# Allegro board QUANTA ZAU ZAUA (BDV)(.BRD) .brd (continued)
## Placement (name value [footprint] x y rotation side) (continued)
R342  EV_SP@100K_5%_4  [R0402]  113.27 80.25 0 top
R343  EV_SP@100K_5%_4  [R0402]  111.87 80.63 90 top
R344  EV_SP@100K_5%_4  [R0402]  88.2 95.62 0 bottom
R345  EV_SP@100K_5%_4  [R0402]  88.2 94.6 0 bottom
R346  EV_SP@100K_5%_4  [R0402]  88.2 96.63 0 bottom
R347  EV_SP@100K_5%_4  [R0402]  88.2 97.65 0 bottom
R348  EV_SP@100K_5%_4  [R0402]  88.37 92.64 0 bottom
R349  EV_SP@100K_5%_4  [R0402]  88.2 93.62 0 bottom
R350  EV_SP@30.1K_1%_4  [R0402]  110.91 82.41 90 top
R351  *EV@100K_5%_4  [R0402]  111.87 82.41 90 top
R352  EV_SP@100K_5%_4  [R0402]  113.27 81.27 180 top
R353  EV_SP@100K_5%_4  [R0402]  90.49 96.76 180 bottom
R354  EV_SP@100K_5%_4  [R0402]  90.49 95.74 180 bottom
R355  EV_SP@100K_5%_4  [R0402]  90.49 97.78 180 bottom
R356  EV_SP@100K_5%_4  [R0402]  90.49 98.79 180 bottom
R357  EV_SP@100K_5%_4  [R0402]  90.49 93.59 180 bottom
R358  EV_SP@100K_5%_4  [R0402]  90.49 94.73 180 bottom
R359  *0_5%_4  [R0402]  176.08 26.15 180 top
R361  4.7K_5%_2  [R0201]  192.57 32.22 90 top
R362  N17@4.7K_5%_4  [R0402]  105.6 85.97 90 top
R363  EV@2.2K_5%_2  [R0201]  95.97 89.65 270 bottom
R364  N17@0_5%_4  [R0402]  94.3 88.12 270 bottom
R365  N17@4.7K_5%_4  [R0402]  104.76 88.38 270 top
R366  EV@2.2K_5%_2  [R0201]  95.26 89.65 270 bottom
R367  EV@2.2K_5%_2  [R0201]  94.55 89.65 270 bottom
R368  EV@2.2K_5%_2  [R0201]  93.84 89.65 270 bottom
R369  4.7K_5%_2  [R0201]  191.84 32.21 90 top
R370  N17@0_5%_2  [R0201]  98.08 96.13 180 top
R372  N17@0_5%_2  [R0201]  88.67 98.83 180 top
R373  N17@0_5%_2  [R0201]  90.23 97.14 180 top
R374  N17@0_5%_2  [R0201]  90.05 93.16 180 top
R376  N17@0_5%_2  [R0201]  90.23 95.72 180 top
R378  EV@10K_1%_4  [R0402]  201.25 16.35 90 top
R380  43_5%_4  [R0402]  179.26 32.24 0 top
R382  *EV@0_5%_4  [R0402]  98.74 123.43 0 top
R383  4.7K_5%_2  [R0201]  190.69 32.29 90 top
R384  *EV@short_4  [S0402]  103.52 123.14 180 top
R385  *EV@4.7K_5%_4  [R0402]  98.74 125.46 180 top
R386  EV@10K_5%_4  [R0402]  91.93 118.15 270 bottom
R391  EV@10K_1%_4  [R0402]  88.2 90.41 0 bottom
R394  EV@10K_1%_4  [R0402]  87.69 99.17 270 top
R395  EV@10K_1%_4  [R0402]  98.74 124.45 0 top
R396  EV@10K_1%_4  [R0402]  96.4 117.79 0 bottom
R397  EV@10K_1%_4  [R0402]  88.07 94.6 0 top
R398  EV@100K_1%_4  [R0402]  89.85 89.39 180 bottom
R399  EV@10K_1%_4  [R0402]  88.23 91.41 0 bottom
R402  *22_5%_4  [R0402]  181.04 23.35 180 top
R403  EV@10K_1%_4  [R0402]  88.07 93.59 0 top
R404  *EV@10K_1%_4  [R0402]  88.07 95.62 0 top
R405  EV@120_1%_4  [R0402]  132.78 97.65 90 bottom
R406  EV@120_1%_4  [R0402]  131.63 102.35 180 bottom
R407  EV@549_1%_4  [R0402]  133.92 100.06 0 top
R410  EV@1.33K_1%_4  [R0402]  133.92 99.05 0 top
R411  EV@931_1%_4  [R0402]  133.92 101.08 0 top
R414  TPC@20K_1%_4  [R0402]  16.57 47.23 90 top
R415  TPC@39K_1%_4  [R0402]  16.57 49.01 90 top
R416  TPC@100K_5%_4  [R0402]  23.56 46.85 90 top
R417  TPC@10K_5%_4  [R0402]  23.94 49.39 0 top
R418  TPC@10K_5%_4  [R0402]  23.94 48.37 0 top
R419  TPC@0_5%_2  [R0201]  20.02 51.69 180 top
R420  TPC@0_5%_2  [R0201]  20.02 52.64 180 top
R421  *short_4  [S0402]  22.54 52.44 180 top
R422  *short_4  [S0402]  22.54 53.45 180 top
R423  *short_4  [S0402]  23.68 57.9 180 top
R424  *short_4  [S0402]  23.68 56.88 180 top
R425  *short_4  [S0402]  22.16 35.17 180 top
R426  *short_4  [S0402]  22.16 34.15 180 top
R427  *short_4  [S0402]  22.16 32.12 180 top
R428  *short_4  [S0402]  22.16 33.13 180 top
R429  *short_4  [S0402]  23.3 36.94 180 top
R430  *short_4  [S0402]  23.3 37.96 180 top
R436  *short_4  [S0402]  57.62 105.93 90 top
R439  *1K_5%_4  [R0402]  53.38 103.57 90 top
R440  *1K_5%_4  [R0402]  58.48 111.82 270 top
R441  1K_1%_4  [R0402]  54.37 103.57 270 top
R442  100K_1%_4  [R0402]  57.69 107.3 180 top
R443  10_5%_4  [R0402]  52.39 103.57 90 top
R445  *short_4  [S0402]  82.1 92.95 180 bottom
R446  100K_1%_4  [R0402]  80.58 94.22 0 bottom
R447  100K_5%_4  [R0402]  202.12 38.47 90 bottom
R448  256@0_5%_4  [R0402]  211.39 31.86 270 top
R449  255@0_5%_4  [R0402]  213.42 32.37 0 top
R450  *short_6  [S0603]  197.83 33.97 0 bottom
R451  200K_1%_4  [R0402]  199.91 30.95 180 top
R452  255@100K_5%_4  [R0402]  200.17 29.97 90 bottom
R453  *256@0_5%_4  [R0402]  210.5 28.59 270 bottom
R454  *255@0_5%_4  [R0402]  211.49 28.59 270 bottom
R455  *short_6  [S0603]  208.39 27.65 0 bottom
R459  *short_4  [S0402]  208.67 26.07 90 bottom
R460  *short_4  [S0402]  202.68 26.9 315 top
R461  22_5%_4  [R0402]  207.71 26.07 270 bottom
R462  *0_5%_4  [R0402]  204.94 24.98 180 top
R463  *short_4  [S0402]  203.41 34.97 90 top
R464  *0_5%_4  [R0402]  210.63 35.67 180 top
R465  *0_5%_4  [R0402]  210.62 39.58 180 top
R467  *0_5%_4  [R0402]  210.63 34.66 180 top
R468  2.2K_5%_4  [R0402]  210.63 41.77 180 top
R469  *0_5%_4  [R0402]  210.63 37.71 180 top
R470  *short_4  [S0402]  207.33 33.87 0 top
R471  2.2K_5%_4  [R0402]  210.63 42.79 180 top
R472  62_1%_4  [R0402]  213.29 46.8 0 top
R473  62_1%_4  [R0402]  215.63 45.5 90 top
R474  *10K_5%_4  [R0402]  211.67 46.87 270 top
R475  *10K_5%_4  [R0402]  214.67 43.78 90 top
R476  4.7K_5%_4  [R0402]  213.29 45.81 180 top
R477  4.7K_5%_4  [R0402]  215.63 43.78 90 top
R478  1K_5%_4  [R0402]  210.98 28.26 180 top
R479  *10K_5%_4  [R0402]  210.83 30.31 270 bottom
R480  *short_6  [S0603]  119.42 17.97 270 top
R481  *short_6  [S0603]  117.99 17.97 270 top
R482  *short_6  [S0603]  116.55 17.97 270 top
R483  *short_6  [S0603]  115.12 17.97 270 top
R484  *150_1%_4  [R0402]  14.79 79.36 90 bottom
R486  *150_1%_4  [R0402]  14.79 77.33 90 bottom
R487  *150_1%_4  [R0402]  14.79 75.3 90 bottom
R489  *150_1%_4  [R0402]  14.79 81.39 90 bottom
R490  2.2K_5%_4  [R0402]  23.61 67.93 90 top
R491  2.2K_5%_4  [R0402]  23.53 69.89 270 top
R494  2.2K_5%_4  [R0402]  18.6 83.81 90 top
R495  *HDD_R@4.7K_5%_4  [R0402]  215.71 13.7 270 top
R497  *HDD_R@4.7K_5%_4  [R0402]  214.69 15.73 90 top
R498  *HDD_R@4.7K_5%_4  [R0402]  214.69 13.7 270 top
R499  HDD_R@4.7K_5%_4  [R0402]  213.68 12.81 90 top
R500  *HDD_R@4.7K_5%_4  [R0402]  215.33 12.31 0 top
R502  2.2K_5%_4  [R0402]  19.75 83.81 90 top
R503  *HDD_R@4.7K_5%_4  [R0402]  206.94 13.45 270 top
R504  HDD_R@4.7K_5%_4  [R0402]  207.07 15.95 0 top
R505  *HDD_R@4.7K_5%_4  [R0402]  205.04 15.1 180 top
R506  HDD_R@4.7K_5%_4  [R0402]  207.07 18.05 180 top
R507  HDMI_R@11K_1%_4  [R0402]  20.89 83.81 270 top
R508  2.49K_1%_4  [R0402]  41.74 109.16 180 top
R509  1K_5%_4  [R0402]  50.28 103.59 90 top
R510  15K_1%_4  [R0402]  48.91 103.59 270 top
R511  10_5%_4  [R0402]  45.88 109.59 90 top
R512  0_5%_4  [R0402]  44.92 109.59 270 top
R513  *short_4  [S0402]  49.8 104.96 0 top
R516  75_1%_8  [R0805]  38.8 111.49 90 top
R517  75_1%_8  [R0805]  35.75 111.49 90 top
R518  75_1%_8  [R0805]  32.7 111.49 90 top
R519  75_1%_8  [R0805]  29.78 111.49 90 top
R557  *0_5%_4  [R0402]  95.49 26.9 270 top
R558  *short_4  [S0402]  94.96 28.75 90 top
R559  4.7K_5%_4  [R0402]  71.18 17.28 90 top
R560  *short_4  [S0402]  93.28 29.62 0 top
R561  *0_5%_4  [R0402]  92.8 28.65 180 top
R562  4.7K_5%_4  [R0402]  72.43 17.28 90 top
R566  4.7K_5%_4  [R0402]  75.68 16.67 0 top
R567  4.7K_5%_4  [R0402]  73.95 16.67 180 top
R572  *short_4  [S0402]  69.84 22.87 180 bottom
R573  *short_4  [S0402]  70.93 15.61 0 top
R574  *10K_5%_4  [R0402]  68.44 23.25 90 bottom
R575  *short_8  [S0805]  175.25 28.36 180 top
R576  1K_5%_4  [R0402]  179.89 29.83 270 top
R579  KBL@10K_5%_4  [R0402]  198.05 19.34 270 bottom
R580  TPM@10K_1%_2  [R0201]  123.23 25.67 0 top
R582  *GS@short_4  [S0402]  50.02 21.45 180 top
R583  TPM@10K_1%_2  [R0201]  121.09 17.74 0 top
R586  TPM@10K_1%_2  [R0201]  121.12 21.14 270 top
R589  *short_4  [S0402]  51.6 18.6 180 top
R590  *GS@short_2  [S0201]  52 20.15 180 top
R591  *GS@short_2  [S0201]  58.23 23.4 180 top
R592  TPM@0_5%_2  [R0201]  126.4 16.55 0 top
R593  TPM@0_5%_2  [R0201]  123 24.57 270 top
R596  TPM@33_5%_2  [R0201]  122.29 24.57 270 top
R597  TPM@33_5%_2  [R0201]  121.65 19.85 0 top
R598  TPM@33_5%_2  [R0201]  121.63 16.42 0 top
R599  TPM@0_5%_2  [R0201]  121.83 21.14 270 top
R600  *TPM@1.2K_5%_2  [R0201]  129.7 20.48 180 top
R601  TPM@0_5%_2  [R0201]  123.73 24.57 270 top
R608  *PBA@0_5%_4  [R0402]  64.6 20.74 0 bottom
R609  PBA@10K_5%_2  [R0201]  66.48 24.67 180 bottom
R614  *short_4  [S0402]  55.59 22.54 180 bottom
R638  ODD@10K_5%_2  [R0201]  129.5 16.52 0 top
R639  *short_8  [S0805]  124.34 18.86 270 bottom
R640  ODD@33_5%_4  [R0402]  136.33 21.37 270 bottom
R641  *ODD@10K_5%_4  [R0402]  135.37 21.37 90 bottom
R645  *SSD@short_2  [S0201]  31.35 2.42 0 top
R646  *SSD@short_2  [S0201]  29.22 11.39 270 bottom
R647  *SSD@short_2  [S0201]  29.98 11.39 270 bottom
R648  *SSD@short_2  [S0201]  28.03 2.42 0 top
R649  SSD@100K_1%_4  [R0402]  23.4 6.31 270 top
R651  4.7K_5%_4  [R0402]  180.83 14.64 180 bottom
R652  4.7K_5%_4  [R0402]  180.83 15.61 180 bottom
R653  *SSD@short_2  [S0201]  13.57 3.19 180 top
R654  *SSD@0_5%_2  [R0201]  22.41 7.56 0 top
R655  *0_5%_4  [R0402]  196.2 18.22 180 bottom
R664  CNV@20K_1%_4  [R0402]  196.07 23.81 135 bottom
R665  CNV@22_1%_4  [R0402]  193.03 25.67 180 bottom
R667  CNV@22_1%_4  [R0402]  193.69 23.28 180 bottom
R670  *short_4  [S0402]  193.31 21.58 180 bottom
R671  *10K_5%_4  [R0402]  193.74 20.53 180 bottom
R672  *10K_5%_4  [R0402]  193.71 19.32 180 bottom
R673  *short_4  [S0402]  193.48 18.15 180 bottom
R674  *short_4  [S0402]  194.83 17.94 270 bottom
R675  *short_4  [S0402]  193.1 16.98 180 bottom
R676  CNV@75K_1%_4  [R0402]  154.11 21.75 270 top
R677  CNV@75K_1%_4  [R0402]  158.89 20.71 90 top
R678  CNV@75K_1%_4  [R0402]  149.06 24.22 0 top
R679  CNV@71.5K_1%_4  [R0402]  147.86 26.53 90 top
R696  *HDMI_R@short_2  [S0201]  16.22 74.76 180 top
R697  *HDMI_R@short_2  [S0201]  16.22 75.83 180 top
R698  *HDMI_R@short_2  [S0201]  16.22 76.67 180 top
R699  *HDMI_R@short_2  [S0201]  16.22 77.74 180 top
R700  *HDMI_R@short_2  [S0201]  16.22 78.83 180 top
R701  *HDMI_R@short_2  [S0201]  16.22 79.89 180 top
R702  *HDMI_R@short_2  [S0201]  16.22 80.86 180 top
R703  *HDMI_R@short_2  [S0201]  16.22 81.93 180 top
R706  HDMI_N@470_1%_2  [R0201]  14.79 81.9 180 top
R707  HDMI_N@470_1%_2  [R0201]  14.79 80.89 180 top
R708  HDMI_N@470_1%_2  [R0201]  14.92 79.87 90 top
R709  HDMI_N@470_1%_2  [R0201]  14.92 78.85 270 top
R710  HDMI_N@470_1%_2  [R0201]  14.79 77.84 180 top
R711  HDMI_N@470_1%_2  [R0201]  14.79 76.82 180 top
R712  HDMI_N@470_1%_2  [R0201]  14.79 75.81 180 top
R713  HDMI_N@470_1%_2  [R0201]  14.79 74.79 180 top
R720  33_5%_4  [R0402]  151.32 21.55 0 top
R732  *100K_5%_4  [R0402]  205.65 27.55 90 bottom
R733  256@100K_5%_4  [R0402]  198.49 30.34 0 bottom
R734  10K_5%_4  [R0402]  199.48 27.14 90 bottom
R735  22K_1%_4  [R0402]  197.22 32.37 270 bottom
R736  255@0_5%_4  [R0402]  195.57 34.38 0 bottom
R737  256@0_5%_4  [R0402]  195.57 35.35 0 bottom
R738  255@0_5%_4  [R0402]  199.91 22.74 90 bottom
R739  256@0_5%_4  [R0402]  199.88 24.57 0 bottom
R740  256@0_5%_4  [R0402]  200.14 25.79 0 bottom
R741  256@3.3K_5%_4  [R0402]  201.36 28.59 180 top
R742  256@3.3K_5%_4  [R0402]  200.82 27.35 0 bottom
R746  *HDMI_R@10K_5%_4  [R0402]  17.61 83.81 270 top
R747  HDMI_R@10K_5%_4  [R0402]  22.9 83.81 90 top
R748  *HDMI_R@0_5%_4  [R0402]  21.91 83.81 270 top
R749  HDMI_R@0_5%_4  [R0402]  16.62 84.24 90 top
R750  *short_4  [S0402]  21.96 85.23 0 top
R775  *short_4  [S0402]  25.08 61.2 180 top
R777  *short_4  [S0402]  25.08 60.18 180 top
R890  100K_5%_2  [R0201]  177.48 17.56 90 top
R894  *short_2  [S0201]  179.69 19.32 270 top
R895  33_5%_2  [R0201]  196.96 31.38 270 top
R956  33_5%_2  [R0201]  202.91 20.69 180 top
R960  33_5%_4  [R0402]  198.21 23.99 270 bottom
R1234  HDD_R@4.7K_5%_4  [R0402]  215.71 15.73 90 top
R1235  HDD_R@4.7K_5%_4  [R0402]  207.07 14.95 0 top
R1236  *HDD_R@4.7K_5%_4  [R0402]  207.07 17.08 0 top
R1237  *HDD_R@4.7K_5%_4  [R0402]  205.04 17.13 180 top
R1238  HDD_R@4.7K_5%_4  [R0402]  205.04 16.12 180 top
R1239  *HDD_R@short_4  [S0402]  206.18 11.54 90 top
R1250  20K_1%_4  [R0402]  18.4 85.66 90 top
R1284  HDMI_N@0_5%_2  [R0201]  25.59 74.92 0 top
R1285  HDMI_N@0_5%_2  [R0201]  25.59 76.06 0 top
R1286  HDMI_N@0_5%_2  [R0201]  25.59 76.82 0 top
R1287  HDMI_N@0_5%_2  [R0201]  25.59 77.96 0 top
R1288  HDMI_N@0_5%_2  [R0201]  25.59 78.73 0 top
R1289  HDMI_N@0_5%_2  [R0201]  25.59 79.87 0 top
R1290  HDMI_N@0_5%_2  [R0201]  25.59 80.63 0 top
R1291  HDMI_N@0_5%_2  [R0201]  25.59 81.77 0 top
R2088  MD@36_1%_4  [R0402]  34.73 101.79 90 top
R2089  MD@36_1%_4  [R0402]  35.77 101.79 90 top
R2090  MD@36_1%_4  [R0402]  33.67 101.79 90 top
R2091  MD@36_1%_4  [R0402]  32.62 101.79 90 top
R2092  MD@36_1%_4  [R0402]  31.58 101.79 90 top
R2099  MD@36_1%_4  [R0402]  41.92 99.86 90 top
R2100  MD@36_1%_4  [R0402]  40.91 99.86 90 top
R2101  MD@36_1%_4  [R0402]  38.95 99.37 90 top
R2102  MD@36_1%_4  [R0402]  32.52 99.4 90 top
R2103  MD@36_1%_4  [R0402]  33.87 99.4 90 top
R2104  MD@36_1%_4  [R0402]  37.93 99.38 90 top
R2105  MD@36_1%_4  [R0402]  35.9 99.4 90 top
R2106  MD@36_1%_4  [R0402]  34.89 99.4 90 top
R2107  MD@36_1%_4  [R0402]  36.91 99.39 90 top
R2109  MD@36_1%_4  [R0402]  38.41 97.21 90 top
R2110  MD@36_1%_4  [R0402]  39.38 97.19 90 top
R2111  MD@36_1%_4  [R0402]  33.59 97.21 90 top
R2112  MD@36_1%_4  [R0402]  29.76 95.8 180 top
R2114  MD@36_1%_4  [R0402]  29.76 94.78 180 top
R2116  MD@36_1%_4  [R0402]  29.76 93.77 180 top
R2117  MD@36_1%_4  [R0402]  29.76 92.75 180 top
R2118  MD@36_1%_4  [R0402]  29.76 91.73 180 top
R2119  MD@36_1%_4  [R0402]  29.76 90.72 180 top
R2121  MD@36_1%_4  [R0402]  29.76 89.7 180 top
R2124  MD@36_1%_4  [R0402]  29.79 88.69 180 top
R2126  MD@36_1%_4  [R0402]  29.77 87.65 180 top
R2130  MD@36_1%_4  [R0402]  29.76 86.63 180 top
R2132  MD@1.8K_1%_4  [R0402]  62.93 82.9 0 top
R2134  MD@0_5%_4  [R0402]  50.4 85.84 180 top
R2135  *MD@0_5%_4  [R0402]  65.06 85.1 0 top
R2136  MD@2.7_5%_6  [R0603]  65.22 83.15 270 top
R2137  MD@36_1%_4  [R0402]  28.94 62.27 90 top
R2138  MD@240_1%_4  [R0402]  50.4 84.82 180 top
R2140  MD@1.8K_1%_4  [R0402]  62.93 84.04 180 top
R2142  MD@24.9_1%_4  [R0402]  62.93 80.99 0 top
R2158  MD@0_5%_4  [R0402]  43.65 68.26 90 top
R2159  MD@240_1%_4  [R0402]  42.56 68.29 90 top
R2160  49.9_1%_4  [R0402]  93.03 78.62 135 top
R2161  49.9_1%_4  [R0402]  94.27 77.41 315 top
R2163  U42@0_5%_4  [R0402]  106.21 73.15 90 top
R2164  U42@0_5%_4  [R0402]  105.14 73.15 90 top
R2165  U23e@0.0002_5%_8  [R0805]  81.27 69.35 90 top
R2166  49.9_1%_4  [R0402]  103.9 72.57 90 top
R2167  240_1%_4  [R0402]  50.35 76.21 0 top
R2168  240_1%_4  [R0402]  55.84 74.38 90 top
R2169  240_1%_4  [R0402]  54.71 74.38 90 top
R2170  *U22@0_5%_4  [R0402]  83.83 70.6 90 top
R2171  24.9_1%_4  [R0402]  93.53 63.16 135 top
R2172  240_1%_4  [R0402]  50.35 75.07 0 top
R2173  240_1%_4  [R0402]  56.97 74.39 90 top
R2174  U22@0.0002_5%_8  [R0805]  90.23 64.24 270 top
R2175  U23e@0.0002_5%_8  [R0805]  88.2 64.24 90 top
R2176  240_1%_4  [R0402]  57.13 71.91 0 top
R2177  240_1%_4  [R0402]  54.94 70.3 180 top
R2178  240_1%_4  [R0402]  55.24 71.91 180 top
R2179  240_1%_4  [R0402]  52.3 73.76 180 top
R2180  240_1%_4  [R0402]  51.41 70.29 180 top
R2181  *U42@0.0002_5%_8  [R0805]  90.26 60.99 90 top
R2182  U42@0.0002_5%_8  [R0805]  86.27 60.96 270 top
R2183  *U42@0.0002_5%_8  [R0805]  84.29 60.97 270 top
R2184  U42@0.0002_5%_8  [R0805]  88.26 60.99 90 top
R2185  *short_4  [S0402]  79.82 59.75 180 top
R2186  *0_5%_2  [R0201]  65.59 62.9 180 top
R2187  240_1%_4  [R0402]  52.21 64.17 90 top
R2190  MD@0_5%_4  [R0402]  43.62 48.09 180 top
R2191  MD@240_1%_4  [R0402]  41.74 48.09 0 top
R2192  24.9_1%_4  [R0402]  52.39 57.87 180 top
R2193  100_1%_4  [R0402]  103.97 48.77 225 top
R2194  100_1%_4  [R0402]  105.29 49.94 225 top
R2195  2_1%_6  [R0603]  53.55 55.26 0 top
R2196  *0_5%_4  [R0402]  50.23 55.31 180 top
R2197  80.6_1%_4  [R0402]  77.39 46.16 90 top
R2198  1K_1%_4  [R0402]  50.23 56.35 180 top
R2199  200_1%_2  [R0201]  80.04 45.56 90 top
R2200  1K_1%_4  [R0402]  50.25 54.34 0 top
R2201  49.9_1%_4  [R0402]  65.92 45.43 180 top
R2202  49.9_1%_4  [R0402]  65.92 44.46 180 top
R2203  100K_5%_2  [R0201]  63 48.14 0 top
R2204  100_1%_2  [R0201]  78.42 43.72 0 top
R2205  100_1%_4  [R0402]  96.99 41.59 0 top
R2206  10K_5%_4  [R0402]  50.25 52.41 0 top
R2207  200_1%_4  [R0402]  90.08 35.85 135 top
R2208  *10K_5%_4  [R0402]  50.25 51.45 180 top
R2209  *short_6  [S0603]  103.95 43.67 270 top
R2212  *short_6  [S0603]  85.48 25.03 0 top
R2213  1K_5%_4  [R0402]  80.43 25.64 90 top
R2214  *short_6  [S0603]  61.94 40.88 0 top
R2216  1M_5%_4  [R0402]  62.8 42.1 0 top
R2217  100_1%_4  [R0402]  94.4 38.11 0 top
R2219  *0_5%_2  [R0201]  35.52 33.56 270 top
R2220  MD@51_1%_4  [R0402]  36.49 33.56 90 top
R2221  MD@0_5%_4  [R0402]  38.49 33.61 90 top
R2222  MD@0_5%_4  [R0402]  44.28 33.6 90 top
R2223  MD@240_1%_4  [R0402]  43.14 33.6 90 top
R2224  *MD@0_5%_4  [R0402]  27.93 62.27 270 top
R2225  8.2K_1%_4  [R0402]  65.9 39.2 225 top
R2227  113_1%_4  [R0402]  89.39 33.11 90 top
R2228  60.4_1%_4  [R0402]  101.03 79.36 180 bottom
R2229  1K_5%_4  [R0402]  101.03 80.38 0 bottom
R2252  *0_5%_2  [R0201]  109.54 29.86 0 top
R2256  *short_2  [S0201]  109.97 28.97 270 top
R2257  *0_5%_2  [R0201]  109.23 28.97 270 top
R2269  *short_4  [S0402]  54.01 31.48 90 top
R2273  *10K_5%_4  [R0402]  52.03 28.15 0 top
R2274  *10K_5%_4  [R0402]  53 31 90 top
R2275  10K_5%_4  [R0402]  52.03 31 270 top
R2278  EV@10K_5%_2  [R0201]  65.47 34.81 0 top
R2279  10K_5%_4  [R0402]  52 29.12 0 top
R2280  *0_5%_6  [R0603]  65.04 22.03 180 top
R2281  10K_5%_2  [R0201]  65.34 35.83 0 top
R2282  *short_6  [S0603]  64.96 23.48 180 top
R2285  *short_2  [S0201]  63.82 35.83 0 top
R2286  10K_5%_2  [R0201]  63.79 34.81 180 top
R2287  *1K_1%_2  [R0201]  78.73 24.12 90 top
R2288  EV@10K_5%_4  [R0402]  78.34 22.49 90 top
R2289  *1K_5%_2  [R0201]  83.2 25.46 0 top
R2290  *150K_5%_4  [R0402]  83.22 24.5 180 top
R2291  *0_5%_6  [R0603]  62.7 24.01 90 top
R2298  *short_6  [S0603]  88.78 28.1 90 top
R2299  *short_6  [S0603]  84.06 29.88 90 top
R2300  *short_6  [S0603]  104.18 34.19 0 top
R2301  10K_5%_2  [R0201]  63.79 36.84 270 top
R2302  100K_5%_2  [R0201]  62.83 29.58 0 top
R2303  *short_6  [S0603]  63.64 26.38 180 top
R2304  10K_5%_2  [R0201]  83.13 26.28 0 top
R2305  *short_2  [S0201]  62.8 36.56 0 top
R2307  *short_2  [S0201]  62.75 34.81 0 top
R2309  *10_5%_4  [R0402]  63.33 28.74 0 top
R2313  *short_6  [S0603]  87.26 29.37 90 top
R2314  *short_6  [S0603]  85.48 26.58 180 top
R2315  *short_6  [S0603]  104.18 35.61 180 top
R2316  *short_6  [S0603]  104.51 31.32 90 top
R2317  *short_6  [S0603]  102.4 35.03 180 bottom
R2318  *short_6  [S0603]  102.5 33.2 180 bottom
R2356  *short_2  [S0201]  201.92 20.69 0 top
R2357  1.5K_1%_4  [R0402]  47.59 25.84 0 top
R2358  45.3K_1%_4  [R0402]  47.99 27.21 90 top
R2359  20K_1%_4  [R0402]  54.47 26.2 180 top
R2360  20K_1%_4  [R0402]  51.04 24.17 180 top
R2378  1K_5%_4  [R0402]  48.7 24.34 270 top
R2448  *100K_5%_2  [R0201]  71.21 80.86 0 bottom
R2449  1K_5%_4  [R0402]  96.83 82.02 270 bottom
R2450  *10K_5%_2  [R0201]  68.85 83.7 270 bottom
R2451  1K_5%_2  [R0201]  98.92 80.57 270 bottom
R2452  499_1%_4  [R0402]  98.66 79.5 0 bottom
R2453  10K_5%_4  [R0402]  97.27 79.89 270 bottom
R2454  *10K_5%_2  [R0201]  98.13 80.57 90 bottom
R2455  100_1%_4  [R0402]  96.3 79.89 90 bottom
R2456  100_1%_4  [R0402]  94.78 79.5 180 bottom
R2457  *0_5%_4  [R0402]  73.16 80.99 180 bottom
R2458  *100K_5%_4  [R0402]  101 76.08 180 bottom
R2459  100_1%_4  [R0402]  101.76 74.38 270 bottom
R2460  220_1%_4  [R0402]  100.8 73.87 90 bottom
R2461  54.9_1%_4  [R0402]  100.8 72.15 90 bottom
R2466  *0_5%_2  [R0201]  104.3 68.95 180 bottom
R2475  100_1%_4  [R0402]  103.44 72.76 0 bottom
R2476  1K_5%_4  [R0402]  101.76 72.66 90 bottom
R2478  *1K_5%_4  [R0402]  105.6 72.76 180 bottom
R2479  49.9_1%_4  [R0402]  102.22 70.93 90 bottom
R2480  51_5%_4  [R0402]  101.97 69.51 180 bottom
R2481  *51_5%_4  [R0402]  100.62 69.58 90 bottom
R2482  *51_5%_4  [R0402]  103.11 68.06 0 bottom
R2483  10K_5%_2  [R0201]  103.32 68.9 180 bottom
R2484  *51_5%_4  [R0402]  105.27 67.93 180 bottom
R2485  *51_5%_4  [R0402]  104.74 66.48 315 bottom
R2486  1K_5%_4  [R0402]  111.19 62.22 180 bottom
R2487  51_5%_4  [R0402]  107.63 68.31 90 bottom
R2488  *0_5%_2  [R0201]  105.6 64.58 0 bottom
R2489  *0_5%_2  [R0201]  105.6 63.84 180 bottom
R2490  2.7K_1%_4  [R0402]  100.7 58.96 270 bottom
R2491  U22@1M_5%_4  [R0402]  101.97 61.33 180 bottom
R2492  100_1%_4  [R0402]  100.75 56 270 bottom
R2493  100_1%_4  [R0402]  102.45 55.18 0 bottom
R2494  1K_1%_2  [R0201]  62.67 46.72 180 bottom
R2495  33_5%_2  [R0201]  64.83 46.72 0 bottom
R2496  33_5%_2  [R0201]  66.74 47.87 0 bottom
R2497  33_5%_2  [R0201]  64.83 45.91 0 bottom
R2498  33_5%_2  [R0201]  66.74 45.25 0 bottom
R2499  *short_6  [S0603]  109.76 47.87 0 top
R2500  *0_5%_2  [R0201]  66.15 42.48 0 bottom
R2501  1.5K_1%_4  [R0402]  95.49 39.58 90 top
R2502  10K_5%_2  [R0201]  64.83 44.03 180 bottom
R2503  *short_2  [S0201]  66.15 44.03 180 bottom
R2504  *short_2  [S0201]  64.83 43.29 0 bottom
R2505  10K_5%_2  [R0201]  64.83 42.51 180 bottom
R2506  *short_6  [S0603]  111.8 48.5 270 top
R2507  *short_2  [S0201]  66.15 43.24 0 bottom
R2508  10K_5%_2  [R0201]  101.84 40.4 90 bottom
R2510  *10K_5%_2  [R0201]  64.83 41.79 0 bottom
R2511  *short_2  [S0201]  103.26 36.25 180 bottom
R2512  *0_5%_2  [R0201]  64.83 41.06 180 bottom
R2514  10K_5%_2  [R0201]  101.84 39.41 270 bottom
R2515  *short_2  [S0201]  67.22 40.45 180 bottom
R2516  8.2K_1%_4  [R0402]  66.15 40.32 270 bottom
R2518  10K_5%_2  [R0201]  67.22 38.59 180 bottom
R2519  10K_5%_2  [R0201]  67.22 39.69 180 bottom
R2521  *short_2  [S0201]  65.82 38.21 0 bottom
R2522  10K_5%_2  [R0201]  102.32 37.17 180 bottom
R2523  *short_2  [S0201]  65.19 37.32 270 bottom
R2524  10K_5%_2  [R0201]  102.27 36.25 180 bottom
R2525  *short_2  [S0201]  67.22 37.04 180 bottom
R2526  470_5%_4  [R0402]  66.76 31.53 180 bottom
R2527  *short_2  [S0201]  67.22 37.81 180 bottom
R2528  *short_2  [S0201]  66.48 30.67 180 bottom
R2529  *short_2  [S0201]  66.36 37.17 270 bottom
R2530  U42@0_5%_4  [R0402]  97.98 31.98 90 bottom
R2531  *short_2  [S0201]  67.22 36.33 180 bottom
R2532  *10K_5%_2  [R0201]  66.48 29.96 180 bottom
R2533  10K_5%_2  [R0201]  99.33 32.64 180 bottom
R2534  U42@1M_5%_4  [R0402]  97.52 30.58 180 bottom
R2535  U42@0_5%_4  [R0402]  97.01 31.98 90 bottom
R2536  8.2K_1%_4  [R0402]  67.19 35.09 90 bottom
R2537  EV@100K_5%_4  [R0402]  71.11 33.21 180 bottom
R2538  *short_2  [S0201]  88.25 32.39 90 bottom
R2539  *short_2  [S0201]  88.96 32.39 90 bottom
R2541  *20K_1%_4  [R0402]  76.11 31.19 90 bottom
R2542  *10K_5%_2  [R0201]  93.28 32.44 90 bottom
R2543  *10K_5%_2  [R0201]  95.46 30.71 270 bottom
R2544  *10K_5%_2  [R0201]  93.48 30.15 0 bottom
R2545  *10K_5%_2  [R0201]  95.46 32.23 90 bottom
R2546  *0_5%_2  [R0201]  67.75 32.63 180 bottom
R2547  *short_2  [S0201]  95.44 29.64 270 bottom
R2548  22_5%_4  [R0402]  64.86 26.66 270 bottom
R2549  IV@1K_5%_4  [R0402]  74.23 32.52 180 bottom
R2551  10K_5%_2  [R0201]  68.79 31.99 180 bottom
R2553  10M_5%_4  [R0402]  79.03 31.11 0 bottom
R2554  10K_5%_2  [R0201]  69.1 33.36 180 bottom
R2555  *1K_1%_2  [R0201]  75.12 31.68 0 bottom
R2557  *10K_5%_2  [R0201]  93.48 30.91 0 bottom
R2558  100K_5%_2  [R0201]  96.79 33.51 0 top
R2559  *100K_5%_2  [R0201]  95.95 35.05 0 top
R2560  TPC_N@10K_5%_4  [R0402]  96.56 31.13 270 top
R2561  1K_5%_4  [R0402]  84.7 32.01 270 bottom
R2562  TPC@10K_5%_4  [R0402]  96.68 29.48 180 top
R2563  *10K_5%_4  [R0402]  90.38 32.01 90 top
R2564  SP@10K_5%_4  [R0402]  91.3 32.01 90 bottom
R2565  SP@10K_5%_4  [R0402]  90.28 32.01 90 bottom
R2566  SP@10K_5%_4  [R0402]  89.85 27.89 270 bottom
R2567  SP@10K_5%_4  [R0402]  88.91 30.72 180 bottom
R2569  22_5%_4  [R0402]  66.23 25.87 0 bottom
R2571  *10K_5%_2  [R0201]  100.85 32.03 180 bottom
R2573  SP@10K_5%_4  [R0402]  91.3 30.28 90 bottom
R2574  SP@10K_5%_4  [R0402]  90.28 30.28 90 bottom
R2575  SP@10K_5%_4  [R0402]  88.48 27.55 0 bottom
R2576  SP@10K_5%_4  [R0402]  88.48 28.51 0 bottom
R2577  10K_5%_4  [R0402]  91.37 30.23 90 top
R2578  *49.9K_1%_2  [R0201]  85.33 28.92 270 bottom
R2579  *49.9K_1%_2  [R0201]  83.04 29.55 180 bottom
R2580  TPM_N@10K_5%_4  [R0402]  102.65 30.48 90 top
R2581  10K_5%_4  [R0402]  95.01 28.04 90 bottom
R2582  10K_5%_4  [R0402]  93.66 27.41 180 bottom
R2583  GS_N@10K_5%_4  [R0402]  92.8 28.65 0 bottom
R2584  200_1%_4  [R0402]  81.88 30.44 0 bottom
R2585  *10K_5%_4  [R0402]  97.93 31.51 0 top
R2586  *short_6  [S0603]  67.98 21.53 90 top
R2587  *0_5%_4  [R0402]  77.07 31.32 90 bottom
R2588  20K_1%_2  [R0201]  98.99 25.01 0 top
R2589  *2.2K_5%_2  [R0201]  99.55 30.56 180 top
R2590  *2.2K_5%_2  [R0201]  99.55 31.29 180 top
R2591  2.2K_5%_4  [R0402]  88.02 29.53 180 bottom
R2592  *1K_1%_2  [R0201]  87.56 30.54 90 bottom
R2593  *0_5%_4  [R0402]  101.64 30.48 270 top
R2594  *10K_5%_4  [R0402]  90.49 28.45 0 top
R2595  10K_5%_4  [R0402]  90.38 30.23 90 top
R2596  *49.9K_1%_2  [R0201]  86.07 28.92 270 bottom
R2597  *49.9K_1%_2  [R0201]  83.68 30.52 180 bottom
R2598  10K_5%_4  [R0402]  98.06 30.14 90 top
R2599  TPM@10K_5%_4  [R0402]  102.02 28.35 0 top
R2600  *10K_5%_4  [R0402]  94.98 25.91 0 bottom
R2601  *10K_5%_4  [R0402]  93.64 26.04 90 bottom
R2602  GS@10K_5%_4  [R0402]  92.67 26.04 90 bottom
R2603  *1K_1%_2  [R0201]  80.73 32.46 0 bottom
R2604  10K_5%_2  [R0201]  100.11 29.42 180 top
R2605  2.2K_5%_4  [R0402]  103.8 28.15 270 bottom
R2606  2.2K_5%_4  [R0402]  99.3 30.86 270 bottom
R2607  2.2K_5%_4  [R0402]  97.62 34.4 0 top
R2608  *0_5%_2  [R0201]  62.04 38.42 0 top
R2609  10K_5%_2  [R0201]  63.03 38.62 180 top
R2610  2.2K_5%_4  [R0402]  102.42 28.45 180 bottom
R2611  15_5%_4  [R0402]  158.15 32.93 0 top
R2612  *10K_5%_2  [R0201]  65.21 36.84 270 top
R2613  *EV@10K_5%_4  [R0402]  81.49 23.58 90 top
R2614  2.2K_5%_4  [R0402]  100.67 28.45 0 bottom
R2615  *10K_5%_2  [R0201]  61.5 36.89 90 top
R2616  15_5%_4  [R0402]  160.21 33.31 270 top
R2617  15_5%_4  [R0402]  158.05 31.51 270 top
R2619  15_5%_4  [R0402]  159.85 29.42 90 top
R2620  1K_5%_2  [R0201]  158.89 29.45 270 top
R2621  15_5%_4  [R0402]  157.92 29.45 270 top
R2622  15_5%_4  [R0402]  160.03 31.53 90 top
R2624  1K_5%_4  [R0402]  162.24 33.11 90 top
R2625  15_5%_4  [R0402]  161.22 33.11 270 top
R2626  15_5%_4  [R0402]  160.82 29.47 90 top
R2627  *short_6  [S0603]  163.08 29.58 270 top
R2628  *short_2  [S0201]  161.86 29.15 180 top
R2630  *0_5%_6  [R0603]  164.53 31.36 270 top
R2631  10K_5%_4  [R0402]  161.99 31.76 0 top
R2648  *EV@10K_5%_4  [R0402]  86.42 96.25 270 bottom
R2649  EV@100K_5%_4  [R0402]  86.42 94.35 90 bottom
R2650  10K_5%_4  [R0402]  79.64 23.74 90 top
R2651  *10K_5%_4  [R0402]  79.08 26.02 180 top
R2652  *SSD@short_2  [S0201]  38.97 11.31 270 bottom
R2653  *SSD@short_2  [S0201]  38.21 11.31 270 bottom
R2654  *SSD@short_2  [S0201]  35.98 11.31 270 bottom
R2655  *SSD@short_2  [S0201]  35.22 11.31 270 bottom
R2656  *SSD@short_2  [S0201]  32.98 11.31 270 bottom
R2657  *SSD@short_2  [S0201]  32.22 11.31 270 bottom
R2658  *SSD@short_2  [S0201]  27.7 11.37 270 bottom
R2659  *SSD@short_2  [S0201]  26.94 11.37 270 bottom
R2660  *SSD@100K_5%_4  [R0402]  29.75 2.53 0 top
R2661  *SSD@short_8  [S0805]  24.93 6.97 270 top
R2662  Debug@0_5%_4  [R0402]  193.03 15.51 180 bottom
R2663  Debug@0_5%_4  [R0402]  193.03 14.54 180 bottom
R2664  Debug@0_5%_4  [R0402]  193.03 13.58 180 bottom
R2665  *short_2  [S0201]  192.52 20.59 90 bottom
R2666  *CNV_N@short_8  [S0805]  193.76 27.65 180 bottom
R2667  CNV@0_5%_8  [R0805]  195.46 12.2 270 bottom
R6504  TPC@100K_1%_4  [R0402]  27.37 17.51 90 bottom
R6505  TPC@100K_1%_4  [R0402]  27.49 19.04 0 bottom
R6506  *TPC@100K_1%_4  [R0402]  26.43 20.29 0 bottom
R6507  *TPC@100K_1%_4  [R0402]  23.3 21.19 270 top
R6508  TPC@100K_1%_4  [R0402]  21.91 18.86 180 bottom
R6510  TPC@100K_1%_4  [R0402]  21.91 17.89 0 bottom
R6515  TPC@100K_1%_4  [R0402]  25.82 11.8 270 bottom
R6516  TPC@100K_1%_4  [R0402]  24.17 11.8 270 bottom
R6517  TPC@100K_1%_4  [R0402]  22.77 12.18 180 bottom
R6603  TPC@10K_1%_4  [R0402]  26.86 13.7 180 top
R9041  *TPC@4.7K_5%_4  [R0402]  27.12 22.27 90 top
R9048  TPC@0_5%_6  [R0603]  21.07 27.57 90 bottom
R25270  *100K_1%_4  [R0402]  60.34 109.92 0 top
R25271  *100K_1%_4  [R0402]  60.34 108.65 0 top
R25272  *TPC@4.7K_5%_4  [R0402]  19.59 25.39 90 bottom
R25273  *TPC@4.7K_5%_4  [R0402]  18.1 18.02 180 bottom
R25274  *TPC@4.7K_5%_4  [R0402]  20.94 25.61 180 bottom
R25275  *TPC@4.7K_5%_4  [R0402]  16.57 25.51 90 bottom
R25276  *TPC@4.7K_5%_4  [R0402]  18.73 19.01 0 bottom
R25277  *TPC@4.7K_5%_4  [R0402]  20.15 20.05 270 bottom
R25278  TPC@4.7K_5%_4  [R0402]  15.56 25.51 270 bottom
R25279  *TPC@4.7K_5%_4  [R0402]  16.85 19.42 270 bottom
R25280  *short_4  [S0402]  20.08 18.32 270 bottom
R25282  EV@1.33K_1%_4  [R0402]  132.65 104.38 180 top
R25283  EV@931_1%_4  [R0402]  134.43 103.11 0 top
R25284  EV@549_1%_4  [R0402]  134.43 104.38 0 top
R25285  *short_8  [S0805]  64.78 110.35 45 top
R25288  *short_4  [S0402]  46.16 103.52 90 bottom
R25289  *short_4  [S0402]  47.18 103.52 90 bottom
R25290  *short_4  [S0402]  44 103.52 90 bottom
R25291  *short_4  [S0402]  45.02 103.52 90 bottom
R25292  TPC@0_5%_4  [R0402]  11.59 11.8 180 top
R25293  TPC@0_5%_4  [R0402]  11.59 10.78 180 top
R25294  HDMI_N@1M_5%_4  [R0402]  19.9 85.23 180 top
R25295  *PBA@@short_4  [S0402]  62.65 21.93 180 top
R25296  *short_8  [S0805]  48.55 112.81 270 top
R25297  *short_4  [S0402]  13.6 86.85 0 top
R25298  100K_5%_2  [R0201]  177.23 21.2 0 top
R25300  100K_5%_4  [R0402]  179.26 22.34 0 top
R25303  *10K_1%_2  [R0201]  194.4 32.22 180 top
R25304  4.7K_5%_2  [R0201]  189.98 32.29 90 top
R25306  2.2_5%_6  [R0603]  176.97 19.42 180 top
R25307  *2.2_5%_6  [R0603]  179.64 27.29 180 top
R25308  33_5%_2  [R0201]  181.16 31.48 180 top
R25309  10K_1%_2  [R0201]  195.26 31.66 90 top
R25310  100K_5%_2  [R0201]  65.01 105.02 270 bottom
R25311  100K_5%_2  [R0201]  201.05 14.01 180 top
R25312  10K_5%_4  [R0402]  169.51 28.31 90 top
R25313  *10K_1%_2  [R0201]  197.14 30.01 90 bottom
R25314  10K_1%_2  [R0201]  193.53 32.09 90 top
R25315  33_5%_2  [R0201]  181.16 29.7 180 top
R25316  *10K_1%_2  [R0201]  194.4 31.51 180 top
R25317  2.2_5%_6  [R0603]  178.95 25.87 180 top
R25318  33_5%_2  [R0201]  193.64 11.26 270 top
R25320  100K_5%_2  [R0201]  182.94 32.37 180 top
R25321  *short_4  [S0402]  22.19 57.77 180 bottom
R25322  N17@10K_1%_4  [R0402]  108.14 83.55 180 top
R25323  *10K_1%_2  [R0201]  180.66 32.37 0 top
R25328  ODD@33_5%_2  [R0201]  201.41 25.72 90 top
R25330  *short_4  [S0402]  177.4 28.36 270 top
R25332  *TPC@0_5%_6  [R0603]  13.27 20.15 270 bottom
R25337  *short_4  [S0402]  15.96 5.27 0 top
R25338  TPC@100K_1%_4  [R0402]  16.85 8.83 270 top
R25339  TPC@10K_1%_4  [R0402]  16.85 10.6 270 top
R25340  TPC@422K_1%_4  [R0402]  17.36 12.79 90 top
R25341  TPC@100K_1%_4  [R0402]  18.76 12.33 0 top
R25342  TPC@470_1%_6  [R0603]  15 11.59 0 top
R25346  TPM@0_5%_6  [R0603]  131.68 20.61 270 top
R25348  TPM@0_5%_6  [R0603]  131.89 16.75 0 top
R25350  HDD_N@0_5%_2  [R0201]  212.28 20.38 90 top
R25351  HDD_N@0_5%_2  [R0201]  211.01 20.38 90 top
R25352  HDD_N@0_5%_2  [R0201]  210.25 20.38 90 top
R25353  HDD_N@0_5%_2  [R0201]  208.98 20.38 90 top
R25355  *GS@10K_1%_2  [R0201]  51.01 20.15 0 top
R25356  *GS@10K_1%_2  [R0201]  60.13 22.08 90 top
R25363  TPC_N@0_5%_8  [R0805]  18.78 44.13 90 bottom
R25364  TPC_N@0_5%_8  [R0805]  16.75 44.13 90 bottom
R25365  *short_4  [S0402]  54.65 108.06 180 top
R25366  *short_4  [S0402]  54.14 106.69 90 top
R25367  10K_5%_4  [R0402]  57.08 112.84 180 top
R25368  10K_5%_4  [R0402]  55.18 109.13 0 top
R25369  100K_5%_4  [R0402]  59.47 111.82 90 top
R25370  *100K_5%_4  [R0402]  55.18 110.1 180 top
R25371  *short_4  [S0402]  195.5 33.42 180 bottom
R25372  10K_5%_4  [R0402]  178.88 29.2 270 top
R25373  10K_5%_4  [R0402]  174.36 30.64 270 top
R25413  2.2K_5%_4  [R0402]  91.88 32.13 270 top
R25415  2.2K_5%_4  [R0402]  95.12 30.59 180 top
R25437  10K_5%_2  [R0201]  102.17 38.49 180 bottom
R25444  *10K_5%_4  [R0402]  58.96 102.2 270 top
R25445  10K_5%_4  [R0402]  59.3 104.01 0 top
R25446  *0_5%_4  [R0402]  60.08 102.2 270 top
R25456  *0_5%_6  [R0603]  61.56 107.1 180 top
R25458  *short_6  [S0603]  62.41 105.37 0 top
R25459  *short_6  [S0603]  59.19 104.89 270 bottom
R25462  *0_5%_6  [R0603]  62.7 101.71 180 top
R25465  *short_6  [S0603]  59.34 106.51 90 top
R25467  33_5%_4  [R0402]  53.76 105.29 180 top
R25469  *EV@short_4  [S0402]  103.49 121.01 180 bottom
R25471  *short_4  [S0402]  69.86 17.28 270 top
R25472  *10K_5%_4  [R0402]  70.06 19.01 90 top
R25473  *short_4  [S0402]  69.1 15.61 0 top
R25474  10K_5%_4  [R0402]  87.51 32.27 0 top
R25475  10K_5%_4  [R0402]  139.74 21.07 180 bottom
R25477  10K_5%_2  [R0201]  87.11 28.64 180 bottom
R25480  *TPC@4.7K_5%_4  [R0402]  99.35 24.01 0 top
R25482  *EV@10K_5%_4  [R0402]  76.74 22.49 270 top
R25483  *HDD@short_2  [S0201]  213.42 10.91 270 top
R25484  *HDD@short_2  [S0201]  210.5 14.21 180 bottom
R25485  GS_N@0_5%_2  [R0201]  214.18 10.91 270 top
R25486  *short_4  [S0402]  39.08 115.05 90 bottom
R25487  *EV@0_5%_4  [R0402]  95.57 121.02 180 bottom
R25488  EV@80.6_1%_4  [R0402]  134.81 97.27 180 bottom
R25489  EV@80.6_1%_4  [R0402]  134.17 102.35 180 bottom
R25490  EV@10K_1%_4  [R0402]  88.07 96.63 0 top
R25492  N16@1.8K_5%_4  [R0402]  92.17 89.01 90 bottom
R25495  *short_4  [S0402]  205.42 29.58 270 top
R25497  33_5%_4  [R0402]  104.79 29.63 270 bottom
R25498  33_5%_4  [R0402]  90.41 25.61 180 bottom
R25502  10K_1%_2  [R0201]  40.24 109.57 90 top
R25503  *short_8  [S0805]  42.02 111.29 90 top
R25504  *HDD@short_8  [S0805]  211.77 18.27 180 bottom
R25505  A5@10K_1%_2  [R0201]  198.69 22.21 90 bottom
R25506  A3@10K_1%_2  [R0201]  198.69 21.07 90 bottom
R25507  N17@0_5%_6  [R0603]  121.85 119.24 0 top
R25508  N17@0_5%_6  [R0603]  121.85 120.76 0 top
R25509  N16@0_5%_6  [R0603]  119.7 120.71 90 top
R25510  N16@0_5%_6  [R0603]  118.17 120.71 90 top
R25511  N16@100K_1%_4  [R0402]  106.41 124.95 270 bottom
R25515  N16@0_5%_6  [R0603]  106.49 119.75 90 top
R25517  N16@0_5%_4  [R0402]  103.82 125.34 0 bottom
R25519  N16@0_5%_4  [R0402]  103.64 123.86 180 bottom
R25520  N17@0_5%_4  [R0402]  100.9 122.92 0 bottom
R25521  N17@0_5%_4  [R0402]  103.77 124.8 270 top
R25522  *EV@short_4  [S0402]  99.5 122.85 270 bottom
R25535  N16@4.7K_5%_4  [R0402]  90.49 100.82 180 bottom
R25537  N16@4.7K_5%_4  [R0402]  87.95 99.66 0 bottom
R25538  N16@1.5K_1%_4  [R0402]  88.38 103.24 90 bottom
R25539  *N16@100K_1%_4  [R0402]  86.88 103.31 0 bottom
R25540  N17@0_5%_4  [R0402]  91.63 87.49 180 bottom
R25546  N16@100K_1%_4  [R0402]  87.82 89.39 180 bottom
R25547  N16@4.7K_5%_4  [R0402]  87.82 88.38 180 bottom
R25548  N16@4.7K_5%_4  [R0402]  84.01 92.72 270 bottom
R25549  N16@4.7K_5%_4  [R0402]  86.56 94.46 90 top
R25550  N17@0_5%_2  [R0201]  85.71 94.01 90 top
R25551  N16@0_5%_2  [R0201]  93.13 89.65 270 bottom
R25552  N16@0_5%_2  [R0201]  95.31 88.63 180 bottom
R25553  N17@0_5%_4  [R0402]  93.28 88.12 270 bottom
R25558  *EV@10K_1%_4  [R0402]  87.69 100.95 270 top
R25560  *EV@short_2  [S0201]  102.27 123.38 270 top
R25561  N16@0_5%_2  [R0201]  90.99 92.57 180 bottom
R25562  N16@0_5%_6  [R0603]  97.85 109.21 270 top
R25563  N16@10K_1%_4  [R0402]  95.68 120.03 0 bottom
R25564  N16@10K_1%_4  [R0402]  105.45 124.95 90 bottom
R25565  N17@0_5%_4  [R0402]  97.27 87.49 270 bottom
R25566  N16@0_5%_4  [R0402]  96.3 87.49 270 bottom
R25567  N16@0_5%_4  [R0402]  88.45 102.86 90 top
R25568  N17@0_5%_4  [R0402]  87.44 102.86 90 top
R25569  N16@0_5%_2  [R0201]  88.69 98.12 180 top
R25570  N16@0_5%_2  [R0201]  89.47 90.41 90 bottom
R25571  N16@0_5%_2  [R0201]  98.08 96.84 180 top
R25572  N16@0_5%_2  [R0201]  90.23 96.43 180 top
R25573  *EV@short_2  [S0201]  88.71 99.68 180 top
R25574  N17@0_5%_4  [R0402]  109.79 82.41 270 top
R25575  N16@0_5%_4  [R0402]  110.65 84.44 90 top
R25576  N16@10K_1%_4  [R0402]  109.69 84.44 270 top
R25577  *EV@short_4  [S0402]  109.79 80.63 270 top
R25579  N17@0_5%_4  [R0402]  88.2 98.64 180 bottom
R25580  N17@0_5%_4  [R0402]  105.73 88.12 90 top
R25581  N16@0_5%_4  [R0402]  105.6 84.21 90 top
R25582  N16@4.7K_5%_4  [R0402]  104.58 85.97 90 top
R25583  N16@4.7K_5%_4  [R0402]  103.11 88.58 270 top
R25584  N16@0_5%_2  [R0201]  96.96 125.46 180 top
R25585  N17@0_5%_2  [R0201]  97.34 124.07 270 top
R25586  TPC@10K_1%_4  [R0402]  26.53 15.35 90 top
R25587  N16@40.2K_1%_4  [R0402]  90.55 106.78 180 bottom
R25588  N16@0_5%_4  [R0402]  86.64 92.63 180 bottom
R25589  *EV@0_5%_2  [R0201]  90.28 93.99 180 top
R25590  TPC@4.7K_5%_4  [R0402]  24.27 21.19 270 top
R25591  N16@0_5%_2  [R0201]  90.28 94.7 180 top
R25592  TPC_N@0_5%_2  [R0201]  21.09 44.13 0 top
R25593  TPC_N@0_5%_2  [R0201]  21.09 45.4 0 top
R25594  TPC@0_5%_2  [R0201]  20.64 44.13 180 top
R25595  TPC@0_5%_2  [R0201]  20.64 45.4 180 top
R25596  TPC_N@0_5%_2  [R0201]  19.57 51.69 0 top
R25597  TPC_N@0_5%_2  [R0201]  19.57 52.64 0 top
R25598  33_5%_4  [R0402]  57.42 103.52 270 bottom
R25599  33_5%_4  [R0402]  57.85 105.27 270 bottom
RV1  TPC@MESD05N92ULA  [DFN1006-3-1X0_6-0_55H-3P]  11.62 11.26 180 bottom
RV2  TPC@AZ1043-04F  [SON10-2_5X1-5-0_55H]  10.98 16.12 270 bottom
RV3  TPC@AZ1043-04F  [SON10-2_5X1-5-0_55H]  10.98 16.12 90 top
SW1  *T3AL-23S-Q-T/R  [SW-T3AL-23-Q-TR-4P]  197.19 27.16 90 bottom
SW2  *NDT016-G1A-KKKT  [SW-NDT016-G1A-KKKT-4P]  19.1 60.62 180 bottom
SW3  RESET_SW  [SW-TME-532-V-6P]  64.85 100.9 270 bottom
TP63  *  [TP2050]  119.7 115.43 180 bottom
TP65  *  [TP2050]  102.02 89.19 0 top
TP66  *  [TP2050]  110.17 85.97 0 top
TP67  *  [TP2050]  103.64 95.97 0 top
TP68  *  [TP2050]  102.31 96.05 0 top
TP69  *  [TP2050]  114.11 82.16 0 top
TP70  *  [TP2050]  97.6 118.35 180 bottom
TP71  *  [TP2050]  97.34 110.86 0 top
TP72  *  [TP2050]  98.94 118.32 180 bottom
TP73  *  [TP2050]  100.21 118.32 180 bottom
TP74  *  [TP2050]  46.72 109.56 180 top
TP75  *  [TP2050]  47.46 110.6 180 top
TP76  *  [TP2050]  48.12 109.28 180 top
TP77  *TPC@PAD  [TP2050]  13.22 12.99 0 top
TP78  *TPC@PAD  [TP2050]  10.2 18.63 0 top
TP81  *PAD  [TP2050]  24.47 2.37 0 top
TP2022  *TP  [TP2050]  66.46 82.38 270 top
TP2023  *TP  [TP2050]  77.99 68.81 270 top
TP2024  *TP  [TP2050]  81.48 65.85 270 top
TP2025  *TP  [TP2050]  94.24 60.56 270 top
TP2026  *TP  [TP2050]  92.95 60 270 top
TP2027  *TP  [TP2050]  92.26 53.12 270 top
TP2028  *TP  [TP2050]  82.76 54.04 270 top
TP2029  *TP  [TP2050]  79.8 48.98 270 top
TP2030  *TP  [TP2050]  80.86 47.76 270 top
TP2031  *TP  [TP2050]  52.92 52.34 270 top
TP2032  *TP  [TP2050]  82.97 44.81 270 top
TP2033  *TP  [TP2050]  75.55 23 270 top
TP2034  *TP  [TP2050]  54.49 51.83 270 top
TP2035  *TP  [TP2050]  80.06 42.37 270 top
TP2036  *TP  [TP2050]  82.08 43.85 270 top
TP2038  *TP  [TP2050]  66.2 42.02 270 top
TP2040  *TP  [TP2050]  66.48 40.42 270 top
TP2042  *TP  [TP2050]  61.07 37.83 270 top
TP2043  *TP  [TP2050]  65.95 33.59 270 top
TP2044  *TP  [TP2050]  64.86 37.91 270 top
TP2046  *TP  [TP2050]  63.59 37.76 270 top
TP2050  *TP  [TP2050]  82.31 25.41 0 top
TP2051  *TP  [TP2050]  82.94 27.09 270 top
TP2071  *TP  [TP2050]  101.41 70.8 90 bottom
TP2072  *TP  [TP2050]  103.17 69.65 90 bottom
TP2073  *TP  [TP2050]  101.13 67.93 90 bottom
TP2074  *TP  [TP2050]  106.79 65.06 90 bottom
TP2075  *TP  [TP2050]  101.13 66.64 90 bottom
TP2076  *TP  [TP2050]  105.57 65.49 90 bottom
TP2077  *TP  [TP2050]  103.34 66.28 90 bottom
TP2078  *TP  [TP2050]  67.27 43.14 90 bottom
TP2079  *TP  [TP2050]  67.24 41.77 90 bottom
TP2080  *TP  [TP2050]  101.23 36.23 90 bottom
TP2081  *TP  [TP2050]  85.48 29.91 0 bottom
TP2083  *TP  [TP2050]  86.75 29.83 0 bottom
TP2084  *TP  [TP2050]  66.76 32.45 90 bottom
TP2085  *TP  [TP2050]  83.93 29.68 0 bottom
TP2086  *TP  [TP2050]  84.57 30.8 0 bottom
TP2088  *TP  [TP2050]  66.36 36.82 90 top
TP2089  *TP  [TP2050]  62.32 37.55 90 top
TP2090  *TP  [TP2050]  186.8 12.71 0 top
TP2091  *TP  [TP2050]  101.13 38.59 180 bottom
TP2092  *PAD  [TP2050]  38.16 2.5 0 top
TP2093  *  [TP2050]  71.36 81.77 180 bottom
TP9000  *TP  [TP2050]  72.93 114.06 0 top
TP9001  *TP  [TP2050]  137.04 31.86 180 bottom
TP9019  *TP  [TP2050]  185.84 31.91 0 top
TP9021  *TP  [TP2050]  181.52 27.19 0 top
TP9023  *  [TP2050]  211.69 27.32 180 bottom
TP9024  *  [TP2050]  209.64 29.09 180 bottom
TP9029  *PAD  [TP2050]  191.17 34.1 180 bottom
TP9030  *  [TP2050]  90.38 112.2 180 bottom
TP9031  *  [TP2050]  90.38 109.41 180 bottom
TP9032  *  [TP2050]  90.38 110.81 180 bottom
TP9033  *  [TP2050]  90.38 108.01 180 bottom
TP9037  *TP  [TP2050]  201.46 23.46 0 top
TP9038  *TP  [TP2050]  181.67 20.31 0 top
TP9039  *TP  [TP2050]  181.49 16.88 0 top
TP9040  *TP  [TP2050]  189.62 10.6 0 top
TP9041  *TP  [TP2050]  180.78 21.27 0 top
TP9051  *PAD  [ESD-6X3]  17.58 55.7 45 top
TP9052  *PAD  [ESD-6X6]  17.32 55.1 90 top
TP9053  *PAD  [ESD-6X3]  17.32 55.43 180 top
TP9054  *PAD  [ESD-6X6]  17.38 55.96 315 top
TP9055  *PAD  [ESD-6X3]  15.8 52.08 0 top
TP9056  *PAD  [ESD-6X6]  15.8 51.83 90 top
TP9057  *PAD  [ESD-6X6]  15.8 52.55 270 top
TP9058  *PAD  [ESD-6X3]  15.8 52.3 0 top
TP9059  *PAD  [ESD-6X3]  16.05 56.73 0 top
TP9060  *PAD  [ESD-6X6]  16.05 56.47 90 top
TP9061  *PAD  [ESD-6X3]  16.05 56.95 0 top
TP9062  *PAD  [ESD-6X6]  16.05 57.2 270 top
TP9063  *PAD  [ESD-6X6]  17.06 34.76 90 top
TP9064  *PAD  [ESD-6X3]  17.06 35.01 0 top
TP9065  *PAD  [ESD-6X3]  17.28 35.45 45 top
TP9066  *PAD  [ESD-6X6]  17.1 35.63 315 top
TP9067  *PAD  [ESD-6X3]  16.06 33.09 0 top
TP9068  *PAD  [ESD-6X6]  16.06 32.84 90 top
TP9069  *PAD  [ESD-6X6]  16.06 33.56 270 top
TP9070  *PAD  [ESD-6X3]  16.06 33.31 0 top
TP9071  *PAD  [ESD-6X3]  16.05 36.71 0 top
TP9072  *PAD  [ESD-6X6]  16.05 36.46 90 top
TP9073  *PAD  [ESD-6X3]  16.04 36.93 0 top
TP9074  *PAD  [ESD-6X6]  16.04 37.19 270 top
U8  EV_SP@N17S-G1-A1  [BGA595-NVIDIA-N13P-GV2-S-A2]  105.03 103.73 90 bottom
U11  EV@NL17SZ32DFT2G  [SOT353-2_1-65-5P]  101.15 120.56 180 bottom
U14  TPC@SLGC55544VTR  [QFN16-3X3-5-17P-TPS2546RTER]  20.13 48.63 0 top
U15  SP@G524B2T11U  [SOT23-5-2_8-95-5P-G708]  19.75 39.86 180 bottom
U16  USB30_ESD_AZ1065-06F.R7G  [ESD10-4_1X2-8-11P]  19.24 55.23 90 top
U17  USB30_ESD_AZ1065-06F.R7G  [ESD10-4_1X2-8-11P]  18.98 34.78 90 top
U18  G524B2T11U  [SOT23-5-2_8-95-5P-G708]  206.31 21.27 0 bottom
U19  APL3512ABI-TRG  [SOT23-5-2_8-95-5P-G708]  83.35 97.36 180 bottom
U20  ALC255-CG  [QFN48-6X6-4-49P-ALC280]  204.66 32.63 180 bottom
U23  HDMI_R@PTN3366BS  [QFN32-5X5-5-37P-0_85H]  20.76 78.47 180 top
U24  RTL8111HSH-CG  [QFN32-4X4-4-33P-0_9H]  44.13 105.4 270 top
U25  NS892407  [TRF-N1010G-25P]  32.4 107.58 180 bottom
U32  GS@LIS3DHTR  [LGA16-3X3-5]  56.58 19.16 180 top
U33  TPM@NPCT750AAAYX  [QFN32-5X5-5-33P-0_85H]  125.69 20.46 90 top
U35  CNV@NL17SZ08DFT2G  [SOT353-1-2_125-65-5P]  156.51 21.17 0 top
U36  CNV@NL17SZ08DFT2G  [SOT353-1-2_125-65-5P]  149.16 21.83 270 top
U37  IT8987E/CX  [LQFP128-16X16-4-1_6H]  191.05 21.98 270 top
U42  HDD_R@SN75LVCP601RTJR  [PWQFN20-4X4-5-26P-0_8H]  210.63 16.37 180 top
U2009  SP@DDR4_96P  [BGA96-MICRON-MT41J64M16JT-187EG]  40.27 89.36 270 top
U2010  SP@DDR4_96P  [BGA96-MICRON-MT41J64M16JT-187EG]  40.27 76.1 270 top
U2011  SP@DDR4_96P  [BGA96-MICRON-MT41J64M16JT-187EG]  40.27 54.69 270 top
U2012  SP@DDR4_96P  [BGA96-MICRON-MT41J64M16JT-187EG]  40.27 41.48 270 top
U2014  MC74VHC1G08DFT2G  [SOT353-1-2_125-65-5P]  108.72 31.48 0 top
U2015  74AUP1G07GW  [SOT353-1-2_125-65-5P]  103.57 25.82 270 top
U2019  MC74VHC1G08DFT2G  [SOT353-1-2_125-65-5P]  63.26 32.52 90 top
U2029  *74AUP1G07GW  [SOT353-1-2_125-65-5P]  104.58 70.98 0 bottom
U2030  SP@BGA1356P  [BGA1356-INTEL-SKYLAKE-U]  86.06 56 180 bottom
U2031  SP@W25Q64FVSSIQ  [SOIC8-7_9-1_27-2_16H]  161.35 29.96 180 bottom
U6502  TPC@PI2EQX632EXUBE_TQFN18  [QFN18-2X2-4-19P-0_4H-SMT]  18.5 22.24 270 bottom
U6503  TPC@TPS25810RVCR(QFN)  [QFN20-4X3-5-27P]  24.75 15.61 270 bottom
U6504  EV@NL17SZ08DFT2G  [SOT353-1-2_125-65-5P]  100.9 124.7 180 bottom
U6505  N16@NL17SZ08DFT2G  [SOT353-1-2_125-65-5P]  117.16 124.7 180 top
VC2  *TVM0G5R5M220R  [C0402]  14.39 88.23 270 top
VRAM1  EV_SP@K4G80325FB-HC28_GDDR5_170P  [BGA170-HYNIX-H5GQ1H24MJR]  133.41 88.6 180 bottom
VRAM2  EV_SP@K4G80325FB-HC28_GDDR5_170P  [BGA170-HYNIX-H5GQ1H24MJR]  133.41 111 0 bottom
Y3  EV@27MHZ/10ppm  [XTL-3_2X2_5-2_2X1_7-0_8H]  100.93 87.34 0 bottom
Y4  25MHZ/30ppm  [XTL-2_05X1_65-1_4X1_1-0_6H]  45.25 113.02 180 top
Y2002  U22@24MHZ/20ppm  [XTL-2X1_6-1_35X1_05]  102.83 64.4 180 bottom
Y2003  U42@24MHZ/20ppm  [XTL-2X1_6-1_35X1_05]  97.67 27.74 180 bottom
Y2004  32.768KHZ/20ppm  [XTL-3_2X1_5-2_5-0_8H]  79.03 28.44 180 bottom

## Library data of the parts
C192-C199 C202 C203 C347-C360 C362-C384 C386-C389 C391-C403 C406-C432 C438-C464 C471-C506 C508-C533 C536 C537 C542-C548 C550 C552-C562 C566 C567 C613 C614 C616 C618 C619 C628 C631-C644 C646 C664 C665 C675-C677 C680-C686 C691 C692 C695-C699 C706-C709 C711 C713-C734 C736 C740 C743 C770-C772 C779 C785 C786 C788-C795 C800-C802 C804 C841 C842 C847-C854 C1189 C1190 C1675-C1693 C2108 C2109 C2111-C2113 C2115 C2119-C2122 C2126-C2128 C2130 C2140-C2145 C2147-C2152 C2154-C2156 C2168-C2170 C2172 C2289 C2297 C2336 C2337 C2342 C2343 C2351 C2363 C2369 C2531-C2540 C2543-C2546 C2573-C2577 C2582 C2583 C2587 C2588 C2593 C2595 C2596 C2599 C2609-C2612 C2616 C6554-C6557 C6565 C6569 C6570 C6573-C6575 C6577 C6578 C6586-C6608 C6615 C6617 C6624 C20000 C20002-C20006 C20016 C20017 C20020-C20023 EC11-EC13 PC1-PC20 PC25 PC35-PC37 PC51 PC81-PC83 PC152 PC164-PC168 PC170 PC172 PC218-PC222 PC224 PC225 PC227-PC236 PC242 PC267 PC268 PC276 PC280 PC283 PC285 PC290 PC292-PC302 PC304-PC306 PC423 PC551 PC561-PC563 PC571 PC572 PC574 PC581 PC756 PC6000-PC6004 PC6006-PC6032 PC6034-PC6059 PC6228-PC6231 PC7003-PC7006 PC7010 PC7020 PC7025 PC7027 PC7029-PC7031 PC7034 PC7035 PC7037-PC7043 PC7046 PC7047 PC7049 PC7053-PC7061 PC7063-PC7066 PC7068-PC7070 PC7072-PC7079 PC7083-PC7093 PC7096 PC7097 PC7099 PC7100 PC7102 PC7104 PC7106 PC9000 PC9003 PC9004 PC9006 PC9008 PC9009 PC9012-PC9014 PC9017-PC9020 PC9022-PC9030 PC9053-PC9060 PC9062-PC9069 PC9071-PC9091 PC9097 PC9098 VC2 = CAP_NON-POL_BGM
C385 C6581 PC162 PC7036 PC7044 PC7045 PC7062 PC7094 PC7095 PC9007 PC9010 PC9011 PC9021 = CAP_POL_BGM
C563-C565 C568 C569 C572-C578 C580 C581 C583-C599 C601-C604 C645 C737 C741 C742 C744 C745 C749 C750 C752 C753 C773-C778 C780-C784 C805 C843-C846 C1044 C1208 C1210 C2063-C2066 C2079-C2082 C2085-C2095 C2097 C2100-C2107 C2110 C2124 C2131-C2139 C2146 C2153 C2157-C2167 C2171 C2173-C2288 C2290-C2296 C2298-C2302 C2305-C2322 C2334 C2335 C2339 C2344-C2350 C2352-C2355 C2357-C2362 C2374 C2418-C2420 C2541 C2542 C2559 C2562-C2570 C2578-C2581 C2584 C2586 C2589-C2592 C2594 C2598 C2601-C2603 C2606-C2608 C6502-C6505 C6544-C6549 C6560 C6562-C6564 C6566 C6568 C6571 C6572 C6580 C6582-C6584 C6610 C6616 C6625 C20024-C20026 EC9 EC10 EC6500 PC217 PC288 PC289 PC6005 PC6033 PC7000 PC7001 PC7007-PC7009 PC7011-PC7019 PC7021-PC7024 PC7026 PC7032 PC7033 PC7050-PC7052 PC7067 PC7080-PC7082 PC7101 PC7103 PC7105 PC9001 PC9002 PC9005 PC9015 PC9016 = CAP NON-POL_BGM
CN1 = Header_2P_BGM
CN2 CN3 = USB3_USB-097-1R09HG_9P_BGM
CN8 = RJ45_8P_4fix_V3_BGM
CN10 = TYPEC_2
CN13 CN24 = FFCFPC_4P_2F_BGM
CN14 CN33 = FFCFPC_8P_BGM
CN15 = FFCFPC_18P_BGM
CN16 = NGFF_79P_MKEY_NAME_BGM
CN17 = NGFF_79P_EKEY_NAME_BGM
CN18 CN19 = FFCFPC_28P_BGM
CN29 CN35 = FFCFPC_40P_BGM
CN36 = FFCFPC_4P_BGM
CN37 = HDMI_19P_10444-19001_BGM
CN38 = HEADER_4P_50208-00401-V02_BGM
D3 D11 D6543 PD9001 = DIODE_BGM
D4 D12 D13 D20 D21 D51 D60-D64 D2016 = Schottky_DIODE_BGM
D14 = BAT54A_BGM
D16-D19 D65 = Varistor_BGM
D22 D33 D50 D13081-D13090 EC7 EC8 = TVS_DIODE_BGM
D2012 PD9002 = BAT54C_BGM
D6541 PD2-PD4 = ZENER_DIODE_BGM
D6542 = ZENER1 DIODE
FAN3 = Header_4P_BGM
HD1 = FFCFPC_12P_V1_BGM
HE1 = HALL_IC_3P_BGM
HOLE1-HOLE4 HOLE11 HOLE13 = 3x2_0.1
HOLE5-HOLE10 HOLE12 HOLE14-HOLE22 = 3x2_1.1
J2000 = OPEN
JDIM2000 = DDR4_264P_BGM
L4 L5 L7 L8 L11-L13 L15 L16 L23 L24 L28-L32 = BEAD_BGM
PJ1 = HEADER_8P_2F_BGM
PJ2 = DCJACK_30706-00042-001_BGM
PJ3005 PJ3008 PJ6001 PJ6003 PJ9002 PJ9005 PR3 PR209 R2165 R2174 R2175 R2181-R2184 = R_Current_SEN_BGM
PJ7001 PR1 PR2 PR208 PR210 PR569 PR6008 PR6026 PR6414 PR7073 PR7074 PR7082 PR7083 PR7088 PR7089 PR7096 PR7097 PR9259 PR9263 PR9266 = SHORTPAD_V01_BGM
